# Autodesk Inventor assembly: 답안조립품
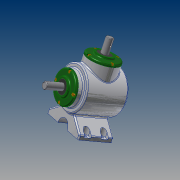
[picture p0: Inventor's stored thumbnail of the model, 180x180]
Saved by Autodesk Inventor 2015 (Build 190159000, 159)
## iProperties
Created: 2017-04
Part Number: 답안조립품
Document SubType Name: Assembly
Designer: owner
Author: owner
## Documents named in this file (14)
- C:\Users\owner\Desktop\470407V1034\답안조립품.iam
- C:\Users\owner\Desktop\470407V1034\메인 베벨기어.ipt
- C:\Users\owner\Desktop\470407V1034\메인 축.ipt
- 메인 축.ipt
- C:\Users\owner\Desktop\470407V1034\베어링 6203.ipt
- C:\Users\owner\Desktop\470407V1034\본체.ipt
- C:\Users\owner\Desktop\470407V1034\볼트 M4.ipt
- C:\Users\owner\Desktop\470407V1034\서브 베벨기어.ipt
- C:\Users\owner\Desktop\470407V1034\서브 축.ipt
- 서브 축.ipt
- C:\Users\owner\Desktop\470407V1034\오일실 17 32 8.ipt
- C:\Users\owner\Desktop\470407V1034\커버.ipt
- C:\Users\owner\Desktop\470407V1034\키 4x4.ipt
- C:\Users\owner\Desktop\470407V1034\키 5x5.ipt
